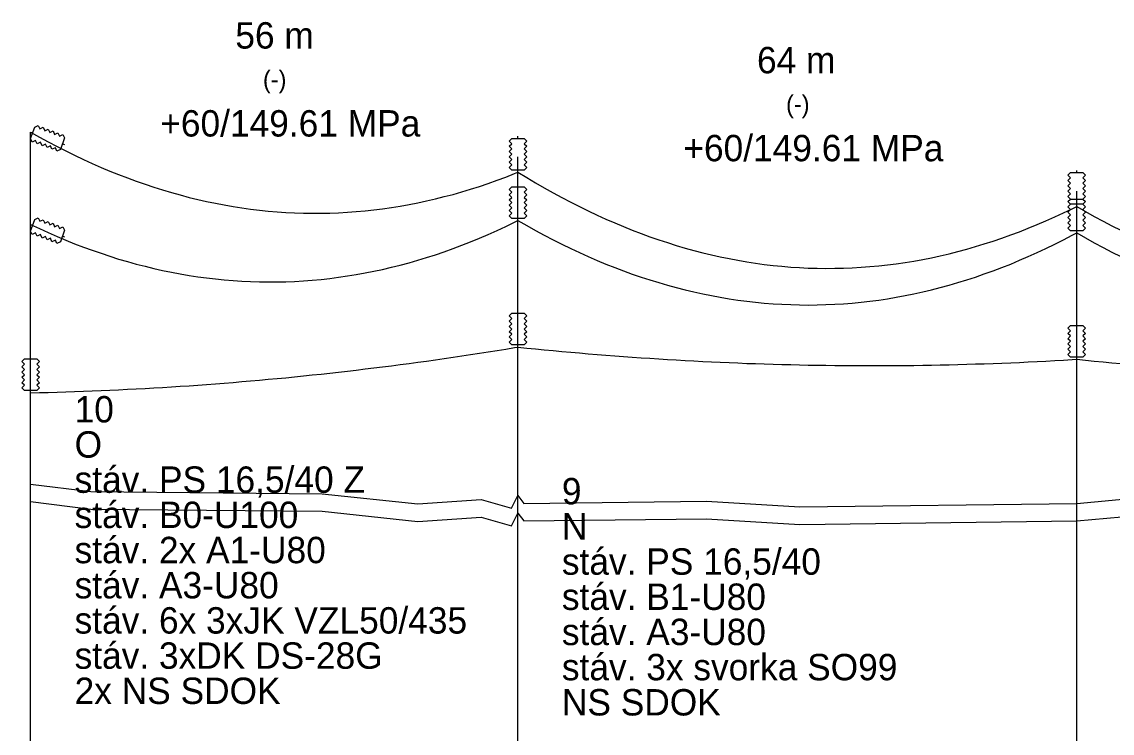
# Model space of a CAD drawing. Extents: x -21 to 625, y 813 to 990.
# Drawn here: x -1 to 122.9, y 899.9 to 980.8 of the extents above; entities that cross this region are included whole.
import ezdxf

# ---------------------------------------------------------------- set-up
doc = ezdxf.new("R2010")
doc.units = 0
for name, color, linetype in [('Vrstva 11', 7, 'Continuous'), ('Vrstva 12', 7, 'Continuous'), ('Vrstva 13', 7, 'Continuous'), ('Vrstva 14', 7, 'Continuous'), ('Vrstva 15', 7, 'Continuous'), ('Vrstva 29', 7, 'Continuous'), ('Vrstva 3', 7, 'Continuous')]:
    doc.layers.add(name, color=color, linetype=linetype)

msp = doc.modelspace()

# ---------------------------------------------------------------- linework, layer by layer
at = {"layer": 'Vrstva 11'}
for points in [[(0, 968.25), (1, 967.69), (2, 967.15), (3, 966.62), (4, 966.11), (5, 965.62), (6, 965.15), (7, 964.69), (8, 964.25), (9, 963.83), (10, 963.43), (11, 963.05), (12, 962.68), (13, 962.33), (14, 962), (15, 961.68), (16, 961.38), (17, 961.11), (18, 960.84), (19, 960.6), (20, 960.37), (21, 960.16), (22, 959.97), (23, 959.8), (24, 959.64), (25, 959.5), (26, 959.38), (27, 959.28), (28, 959.2), (29, 959.13), (30, 959.08), (31, 959.04), (32, 959.03), (33, 959.03), (34, 959.05), (35, 959.09), (36, 959.14), (37, 959.22), (38, 959.31), (39, 959.42), (40, 959.54), (41, 959.69), (42, 959.85), (43, 960.03), (44, 960.22), (45, 960.44), (46, 960.67), (47, 960.92), (48, 961.18), (49, 961.47), (50, 961.77), (51, 962.09), (52, 962.43), (53, 962.78), (54, 963.15), (55, 963.54), (55.37, 963.69)], [(55.37, 963.69), (56.37, 963.08), (57.37, 962.49), (58.37, 961.91), (59.37, 961.35), (60.37, 960.81), (61.37, 960.29), (62.37, 959.78), (63.37, 959.29), (64.37, 958.82), (65.37, 958.37), (66.37, 957.93), (67.37, 957.51), (68.37, 957.11), (69.37, 956.73), (70.37, 956.36), (71.37, 956.02), (72.37, 955.69), (73.37, 955.37), (74.37, 955.08), (75.37, 954.8), (76.37, 954.54), (77.37, 954.3), (78.37, 954.08), (79.37, 953.87), (80.37, 953.68), (81.37, 953.51), (82.37, 953.36), (83.37, 953.22), (84.37, 953.1), (85.37, 953), (86.37, 952.92), (87.37, 952.85), (88.37, 952.8), (89.37, 952.77), (90.37, 952.76), (91.37, 952.77), (92.37, 952.79), (93.37, 952.83), (94.37, 952.89), (95.37, 952.96), (96.37, 953.05), (97.37, 953.16), (98.37, 953.29), (99.37, 953.44), (100.37, 953.6), (101.37, 953.78), (102.37, 953.98), (103.37, 954.2), (104.37, 954.43), (105.37, 954.68), (106.37, 954.95), (107.37, 955.24), (108.37, 955.54), (109.37, 955.86), (110.37, 956.2), (111.37, 956.56), (112.37, 956.93), (113.37, 957.33), (114.37, 957.74), (115.37, 958.16), (116.37, 958.61), (117.37, 959.07), (118.37, 959.55), (118.87, 959.8)], [(118.87, 959.8), (119.87, 959.23), (120.87, 958.67), (121.87, 958.13), (122.87, 957.61), (123.87, 957.1)], [(0, 957.75), (1, 957.28), (2, 956.83), (3, 956.39), (4, 955.97), (5, 955.57), (6, 955.19), (7, 954.82), (8, 954.48), (9, 954.15), (10, 953.83), (11, 953.54), (12, 953.26), (13, 953), (14, 952.76), (15, 952.54), (16, 952.33), (17, 952.14), (18, 951.97), (19, 951.82), (20, 951.68), (21, 951.56), (22, 951.46), (23, 951.38), (24, 951.31), (25, 951.26), (26, 951.23), (27, 951.22), (28, 951.22), (29, 951.25), (30, 951.29), (31, 951.34), (32, 951.42), (33, 951.51), (34, 951.62), (35, 951.75), (36, 951.9), (37, 952.06), (38, 952.24), (39, 952.44), (40, 952.65), (41, 952.89), (42, 953.14), (43, 953.41), (44, 953.7), (45, 954), (46, 954.32), (47, 954.66), (48, 955.02), (49, 955.39), (50, 955.79), (51, 956.19), (52, 956.62), (53, 957.07), (54, 957.53), (55, 958.01), (55.37, 958.19)], [(0, 957.75), (1, 957.28), (2, 956.83), (3, 956.39), (4, 955.97), (5, 955.57), (6, 955.19), (7, 954.82), (8, 954.48), (9, 954.15), (10, 953.83), (11, 953.54), (12, 953.26), (13, 953), (14, 952.76), (15, 952.54), (16, 952.33), (17, 952.14), (18, 951.97), (19, 951.82), (20, 951.68), (21, 951.56), (22, 951.46), (23, 951.38), (24, 951.31), (25, 951.26), (26, 951.23), (27, 951.22), (28, 951.22), (29, 951.25), (30, 951.29), (31, 951.34), (32, 951.42), (33, 951.51), (34, 951.62), (35, 951.75), (36, 951.9), (37, 952.06), (38, 952.24), (39, 952.44), (40, 952.65), (41, 952.89), (42, 953.14), (43, 953.41), (44, 953.7), (45, 954), (46, 954.32), (47, 954.66), (48, 955.02), (49, 955.39), (50, 955.79), (51, 956.19), (52, 956.62), (53, 957.07), (54, 957.53), (55, 958.01), (55.37, 958.19)], [(55.37, 958.19), (56.37, 957.62), (57.37, 957.06), (58.37, 956.53), (59.37, 956.01), (60.37, 955.51), (61.37, 955.02), (62.37, 954.56), (63.37, 954.11), (64.37, 953.67), (65.37, 953.26), (66.37, 952.86), (67.37, 952.49), (68.37, 952.12), (69.37, 951.78), (70.37, 951.46), (71.37, 951.15), (72.37, 950.86), (73.37, 950.58), (74.37, 950.33), (75.37, 950.09), (76.37, 949.87), (77.37, 949.67), (78.37, 949.48), (79.37, 949.32), (80.37, 949.17), (81.37, 949.03), (82.37, 948.92), (83.37, 948.82), (84.37, 948.74), (85.37, 948.68), (86.37, 948.64), (87.37, 948.61), (88.37, 948.6), (89.37, 948.61), (90.37, 948.64), (91.37, 948.68), (92.37, 948.74), (93.37, 948.82), (94.37, 948.92), (95.37, 949.04), (96.37, 949.17), (97.37, 949.32), (98.37, 949.48), (99.37, 949.67), (100.37, 949.87), (101.37, 950.09), (102.37, 950.33), (103.37, 950.59), (104.37, 950.86), (105.37, 951.15), (106.37, 951.46), (107.37, 951.78), (108.37, 952.13), (109.37, 952.49), (110.37, 952.87), (111.37, 953.26), (112.37, 953.68), (113.37, 954.11), (114.37, 954.56), (115.37, 955.03), (116.37, 955.51), (117.37, 956.01), (118.37, 956.53), (118.87, 956.8)], [(55.37, 958.19), (56.37, 957.62), (57.37, 957.06), (58.37, 956.53), (59.37, 956.01), (60.37, 955.51), (61.37, 955.02), (62.37, 954.56), (63.37, 954.11), (64.37, 953.67), (65.37, 953.26), (66.37, 952.86), (67.37, 952.49), (68.37, 952.12), (69.37, 951.78), (70.37, 951.46), (71.37, 951.15), (72.37, 950.86), (73.37, 950.58), (74.37, 950.33), (75.37, 950.09), (76.37, 949.87), (77.37, 949.67), (78.37, 949.48), (79.37, 949.32), (80.37, 949.17), (81.37, 949.03), (82.37, 948.92), (83.37, 948.82), (84.37, 948.74), (85.37, 948.68), (86.37, 948.64), (87.37, 948.61), (88.37, 948.6), (89.37, 948.61), (90.37, 948.64), (91.37, 948.68), (92.37, 948.74), (93.37, 948.82), (94.37, 948.92), (95.37, 949.04), (96.37, 949.17), (97.37, 949.32), (98.37, 949.48), (99.37, 949.67), (100.37, 949.87), (101.37, 950.09), (102.37, 950.33), (103.37, 950.59), (104.37, 950.86), (105.37, 951.15), (106.37, 951.46), (107.37, 951.78), (108.37, 952.13), (109.37, 952.49), (110.37, 952.87), (111.37, 953.26), (112.37, 953.68), (113.37, 954.11), (114.37, 954.56), (115.37, 955.03), (116.37, 955.51), (117.37, 956.01), (118.37, 956.53), (118.87, 956.8)], [(118.87, 956.8), (119.87, 956.23), (120.87, 955.67), (121.87, 955.13), (122.87, 954.61), (123.87, 954.1)], [(118.87, 956.8), (119.87, 956.23), (120.87, 955.67), (121.87, 955.13), (122.87, 954.61), (123.87, 954.1)], [(0, 938.62), (1, 938.65), (2, 938.67), (3, 938.7), (4, 938.73), (5, 938.76), (6, 938.8), (7, 938.84), (8, 938.88), (9, 938.92), (10, 938.97), (11, 939.02), (12, 939.07), (13, 939.12), (14, 939.18), (15, 939.24), (16, 939.3), (17, 939.37), (18, 939.43), (19, 939.5), (20, 939.58), (21, 939.65), (22, 939.73), (23, 939.81), (24, 939.89), (25, 939.98), (26, 940.06), (27, 940.16), (28, 940.25), (29, 940.34), (30, 940.44), (31, 940.54), (32, 940.65), (33, 940.75), (34, 940.86), (35, 940.97), (36, 941.09), (37, 941.21), (38, 941.33), (39, 941.45), (40, 941.57), (41, 941.7), (42, 941.83), (43, 941.96), (44, 942.1), (45, 942.23), (46, 942.38), (47, 942.52), (48, 942.66), (49, 942.81), (50, 942.96), (51, 943.12), (52, 943.27), (53, 943.43), (54, 943.59), (55, 943.76), (55.37, 943.82)], [(55.37, 943.82), (56.37, 943.71), (57.37, 943.61), (58.37, 943.51), (59.37, 943.42), (60.37, 943.33), (61.37, 943.23), (62.37, 943.15), (63.37, 943.06), (64.37, 942.98), (65.37, 942.9), (66.37, 942.82), (67.37, 942.75), (68.37, 942.67), (69.37, 942.6), (70.37, 942.54), (71.37, 942.47), (72.37, 942.41), (73.37, 942.35), (74.37, 942.3), (75.37, 942.24), (76.37, 942.19), (77.37, 942.14), (78.37, 942.1), (79.37, 942.05), (80.37, 942.01), (81.37, 941.97), (82.37, 941.94), (83.37, 941.9), (84.37, 941.87), (85.37, 941.85), (86.37, 941.82), (87.37, 941.8), (88.37, 941.78), (89.37, 941.76), (90.37, 941.75), (91.37, 941.73), (92.37, 941.73), (93.37, 941.72), (94.37, 941.71), (95.37, 941.71), (96.37, 941.71), (97.37, 941.72), (98.37, 941.72), (99.37, 941.73), (100.37, 941.74), (101.37, 941.76), (102.37, 941.77), (103.37, 941.79), (104.37, 941.81), (105.37, 941.84), (106.37, 941.87), (107.37, 941.9), (108.37, 941.93), (109.37, 941.96), (110.37, 942), (111.37, 942.04), (112.37, 942.08), (113.37, 942.13), (114.37, 942.18), (115.37, 942.23), (116.37, 942.28), (117.37, 942.34), (118.37, 942.39), (118.87, 942.43)], [(118.87, 942.43), (119.87, 942.32), (120.87, 942.23), (121.87, 942.13), (122.87, 942.04), (123.87, 941.95)]]:
    msp.add_lwpolyline(points, dxfattribs=at)
at = {"layer": 'Vrstva 14'}
for p, q in [((0, 898.25), (0, 968.25)), ((55.37, 896.94), (55.37, 965.44)), ((118.87, 896.05), (118.87, 961.55))]:
    msp.add_line(p, q, dxfattribs=at)
at = {"layer": 'Vrstva 29'}
for points in [[(0, 967.51), (0.47, 968.82), (0.86, 969), (1.04, 968.62), (1.42, 968.8), (1.6, 968.41), (1.99, 968.59), (2.17, 968.21), (2.55, 968.39), (2.73, 968), (3.11, 968.18), (3.29, 967.8), (3.68, 967.98), (3.86, 967.59), (3.38, 966.28), (2.99, 966.1), (2.81, 966.48), (2.43, 966.3), (2.25, 966.69), (1.87, 966.51), (1.69, 966.89), (1.3, 966.71), (1.12, 967.1), (0.74, 966.92), (0.56, 967.3), (0.17, 967.12)], [(56.07, 963.94), (54.67, 963.94), (54.37, 964.24), (54.67, 964.54), (54.37, 964.84), (54.67, 965.14), (54.37, 965.44), (54.67, 965.74), (54.37, 966.04), (54.67, 966.34), (54.37, 966.64), (54.67, 966.94), (54.37, 967.24), (54.67, 967.54), (56.07, 967.54), (56.37, 967.24), (56.07, 966.94), (56.37, 966.64), (56.07, 966.34), (56.37, 966.04), (56.07, 965.74), (56.37, 965.44), (56.07, 965.14), (56.37, 964.84), (56.07, 964.54), (56.37, 964.24)], [(56.07, 963.94), (54.67, 963.94), (54.37, 964.24), (54.67, 964.54), (54.37, 964.84), (54.67, 965.14), (54.37, 965.44), (54.67, 965.74), (54.37, 966.04), (54.67, 966.34), (54.37, 966.64), (54.67, 966.94), (54.37, 967.24), (54.67, 967.54), (56.07, 967.54), (56.37, 967.24), (56.07, 966.94), (56.37, 966.64), (56.07, 966.34), (56.37, 966.04), (56.07, 965.74), (56.37, 965.44), (56.07, 965.14), (56.37, 964.84), (56.07, 964.54), (56.37, 964.24)], [(119.57, 960.05), (118.17, 960.05), (117.87, 960.35), (118.17, 960.65), (117.87, 960.95), (118.17, 961.25), (117.87, 961.55), (118.17, 961.85), (117.87, 962.15), (118.17, 962.45), (117.87, 962.75), (118.17, 963.05), (117.87, 963.35), (118.17, 963.65), (119.57, 963.65), (119.87, 963.35), (119.57, 963.05), (119.87, 962.75), (119.57, 962.45), (119.87, 962.15), (119.57, 961.85), (119.87, 961.55), (119.57, 961.25), (119.87, 960.95), (119.57, 960.65), (119.87, 960.35)], [(56.07, 958.44), (54.67, 958.44), (54.37, 958.74), (54.67, 959.04), (54.37, 959.34), (54.67, 959.64), (54.37, 959.94), (54.67, 960.24), (54.37, 960.54), (54.67, 960.84), (54.37, 961.14), (54.67, 961.44), (54.37, 961.74), (54.67, 962.04), (56.07, 962.04), (56.37, 961.74), (56.07, 961.44), (56.37, 961.14), (56.07, 960.84), (56.37, 960.54), (56.07, 960.24), (56.37, 959.94), (56.07, 959.64), (56.37, 959.34), (56.07, 959.04), (56.37, 958.74)], [(56.07, 958.44), (54.67, 958.44), (54.37, 958.74), (54.67, 959.04), (54.37, 959.34), (54.67, 959.64), (54.37, 959.94), (54.67, 960.24), (54.37, 960.54), (54.67, 960.84), (54.37, 961.14), (54.67, 961.44), (54.37, 961.74), (54.67, 962.04), (56.07, 962.04), (56.37, 961.74), (56.07, 961.44), (56.37, 961.14), (56.07, 960.84), (56.37, 960.54), (56.07, 960.24), (56.37, 959.94), (56.07, 959.64), (56.37, 959.34), (56.07, 959.04), (56.37, 958.74)], [(56.07, 958.44), (54.67, 958.44), (54.37, 958.74), (54.67, 959.04), (54.37, 959.34), (54.67, 959.64), (54.37, 959.94), (54.67, 960.24), (54.37, 960.54), (54.67, 960.84), (54.37, 961.14), (54.67, 961.44), (54.37, 961.74), (54.67, 962.04), (56.07, 962.04), (56.37, 961.74), (56.07, 961.44), (56.37, 961.14), (56.07, 960.84), (56.37, 960.54), (56.07, 960.24), (56.37, 959.94), (56.07, 959.64), (56.37, 959.34), (56.07, 959.04), (56.37, 958.74)], [(56.07, 958.44), (54.67, 958.44), (54.37, 958.74), (54.67, 959.04), (54.37, 959.34), (54.67, 959.64), (54.37, 959.94), (54.67, 960.24), (54.37, 960.54), (54.67, 960.84), (54.37, 961.14), (54.67, 961.44), (54.37, 961.74), (54.67, 962.04), (56.07, 962.04), (56.37, 961.74), (56.07, 961.44), (56.37, 961.14), (56.07, 960.84), (56.37, 960.54), (56.07, 960.24), (56.37, 959.94), (56.07, 959.64), (56.37, 959.34), (56.07, 959.04), (56.37, 958.74)], [(119.57, 957.05), (118.17, 957.05), (117.87, 957.35), (118.17, 957.65), (117.87, 957.95), (118.17, 958.25), (117.87, 958.55), (118.17, 958.85), (117.87, 959.15), (118.17, 959.45), (117.87, 959.75), (118.17, 960.05), (117.87, 960.35), (118.17, 960.65), (119.57, 960.65), (119.87, 960.35), (119.57, 960.05), (119.87, 959.75), (119.57, 959.45), (119.87, 959.15), (119.57, 958.85), (119.87, 958.55), (119.57, 958.25), (119.87, 957.95), (119.57, 957.65), (119.87, 957.35)], [(119.57, 957.05), (118.17, 957.05), (117.87, 957.35), (118.17, 957.65), (117.87, 957.95), (118.17, 958.25), (117.87, 958.55), (118.17, 958.85), (117.87, 959.15), (118.17, 959.45), (117.87, 959.75), (118.17, 960.05), (117.87, 960.35), (118.17, 960.65), (119.57, 960.65), (119.87, 960.35), (119.57, 960.05), (119.87, 959.75), (119.57, 959.45), (119.87, 959.15), (119.57, 958.85), (119.87, 958.55), (119.57, 958.25), (119.87, 957.95), (119.57, 957.65), (119.87, 957.35)], [(0, 957.01), (0.47, 958.32), (0.86, 958.5), (1.04, 958.12), (1.42, 958.3), (1.6, 957.91), (1.99, 958.09), (2.17, 957.71), (2.55, 957.89), (2.73, 957.5), (3.11, 957.68), (3.29, 957.3), (3.68, 957.48), (3.86, 957.09), (3.38, 955.78), (2.99, 955.6), (2.81, 955.98), (2.43, 955.8), (2.25, 956.19), (1.87, 956.01), (1.69, 956.39), (1.3, 956.21), (1.12, 956.6), (0.74, 956.42), (0.56, 956.8), (0.17, 956.62)], [(0, 957.01), (0.47, 958.32), (0.86, 958.5), (1.04, 958.12), (1.42, 958.3), (1.6, 957.91), (1.99, 958.09), (2.17, 957.71), (2.55, 957.89), (2.73, 957.5), (3.11, 957.68), (3.29, 957.3), (3.68, 957.48), (3.86, 957.09), (3.38, 955.78), (2.99, 955.6), (2.81, 955.98), (2.43, 955.8), (2.25, 956.19), (1.87, 956.01), (1.69, 956.39), (1.3, 956.21), (1.12, 956.6), (0.74, 956.42), (0.56, 956.8), (0.17, 956.62)], [(56.07, 944.07), (54.67, 944.07), (54.37, 944.37), (54.67, 944.67), (54.37, 944.97), (54.67, 945.27), (54.37, 945.57), (54.67, 945.87), (54.37, 946.17), (54.67, 946.47), (54.37, 946.77), (54.67, 947.07), (54.37, 947.37), (54.67, 947.67), (56.07, 947.67), (56.37, 947.37), (56.07, 947.07), (56.37, 946.77), (56.07, 946.47), (56.37, 946.17), (56.07, 945.87), (56.37, 945.57), (56.07, 945.27), (56.37, 944.97), (56.07, 944.67), (56.37, 944.37)], [(119.57, 942.68), (118.17, 942.68), (117.87, 942.98), (118.17, 943.27), (117.87, 943.58), (118.17, 943.88), (117.87, 944.18), (118.17, 944.48), (117.87, 944.77), (118.17, 945.08), (117.87, 945.38), (118.17, 945.68), (117.87, 945.98), (118.17, 946.27), (119.57, 946.27), (119.87, 945.98), (119.57, 945.68), (119.87, 945.38), (119.57, 945.08), (119.87, 944.77), (119.57, 944.48), (119.87, 944.18), (119.57, 943.88), (119.87, 943.58), (119.57, 943.27), (119.87, 942.98)], [(0.7, 938.88), (-0.7, 938.88), (-1, 939.18), (-0.7, 939.48), (-1, 939.77), (-0.7, 940.08), (-1, 940.38), (-0.7, 940.68), (-1, 940.98), (-0.7, 941.27), (-1, 941.58), (-0.7, 941.88), (-1, 942.18), (-0.7, 942.48), (0.7, 942.48), (1, 942.18), (0.7, 941.88), (1, 941.58), (0.7, 941.27), (1, 940.98), (0.7, 940.68), (1, 940.38), (0.7, 940.08), (1, 939.77), (0.7, 939.48), (1, 939.18)]]:
    msp.add_lwpolyline(points, close=True, dxfattribs=at)
for points in [[(0, 968.25), (0.23, 968.16)], [(55.37, 967.54), (55.37, 967.79)], [(55.37, 967.54), (55.37, 967.79)], [(3.62, 966.93), (3.85, 966.85)], [(55.37, 963.69), (55.37, 963.94)], [(55.37, 963.69), (55.37, 963.94)], [(118.87, 963.65), (118.87, 963.9)], [(55.37, 962.04), (55.37, 962.29)], [(55.37, 962.04), (55.37, 962.29)], [(55.37, 962.04), (55.37, 962.29)], [(55.37, 962.04), (55.37, 962.29)], [(118.87, 960.65), (118.87, 960.9)], [(118.87, 960.65), (118.87, 960.9)], [(118.87, 959.8), (118.87, 960.05)], [(55.37, 958.19), (55.37, 958.44)], [(55.37, 958.19), (55.37, 958.44)], [(55.37, 958.19), (55.37, 958.44)], [(55.37, 958.19), (55.37, 958.44)], [(0, 957.75), (0.23, 957.66)], [(0, 957.75), (0.23, 957.66)], [(118.87, 956.8), (118.87, 957.05)], [(118.87, 956.8), (118.87, 957.05)], [(3.62, 956.43), (3.85, 956.35)], [(3.62, 956.43), (3.85, 956.35)], [(55.37, 947.67), (55.37, 947.92)], [(118.87, 946.27), (118.87, 946.52)], [(55.37, 943.82), (55.37, 944.07)], [(0, 942.48), (0, 942.73)], [(118.87, 942.43), (118.87, 942.68)], [(0, 938.62), (0, 938.88)]]:
    msp.add_lwpolyline(points, dxfattribs=at)
at = {"layer": 'Vrstva 3'}
for p, q in [((0, 928.25), (6.86, 927.4)), ((6.86, 927.4), (33.13, 927.15)), ((33.13, 927.15), (43.99, 926)), ((54.66, 925.5), (55.36, 926.95)), ((55.36, 926.95), (55.37, 926.94)), ((55.37, 926.94), (56.06, 926.05)), ((118.87, 926.05), (136.97, 927.7)), ((0, 926.25), (6.86, 925.4)), ((0, 926.25), (6.86, 925.4)), ((0, 926.25), (6.86, 925.4)), ((43.99, 926), (51.19, 926.5)), ((51.19, 926.5), (54.66, 925.5)), ((56.06, 926.05), (76.8, 926.3)), ((76.8, 926.3), (87.41, 925.65)), ((87.41, 925.65), (118.87, 926.05)), ((118.87, 924.05), (136.97, 925.7)), ((118.87, 924.05), (136.97, 925.7)), ((118.87, 924.05), (136.97, 925.7)), ((6.86, 925.4), (33.13, 925.15)), ((6.86, 925.4), (33.13, 925.15)), ((6.86, 925.4), (33.13, 925.15)), ((33.13, 925.15), (43.99, 924)), ((33.13, 925.15), (43.99, 924)), ((33.13, 925.15), (43.99, 924)), ((43.99, 924), (51.19, 924.5)), ((43.99, 924), (51.19, 924.5)), ((43.99, 924), (51.19, 924.5)), ((51.19, 924.5), (54.66, 923.5)), ((51.19, 924.5), (54.66, 923.5)), ((51.19, 924.5), (54.66, 923.5)), ((54.66, 923.5), (55.36, 924.95)), ((54.66, 923.5), (55.36, 924.95)), ((54.66, 923.5), (55.36, 924.95)), ((55.36, 924.95), (55.37, 924.94)), ((55.36, 924.95), (55.37, 924.94)), ((55.36, 924.95), (55.37, 924.94)), ((55.37, 924.94), (56.06, 924.05)), ((55.37, 924.94), (56.06, 924.05)), ((55.37, 924.94), (56.06, 924.05)), ((56.06, 924.05), (76.8, 924.3)), ((56.06, 924.05), (76.8, 924.3)), ((56.06, 924.05), (76.8, 924.3)), ((76.8, 924.3), (87.41, 923.65)), ((76.8, 924.3), (87.41, 923.65)), ((76.8, 924.3), (87.41, 923.65)), ((87.41, 923.65), (118.87, 924.05)), ((87.41, 923.65), (118.87, 924.05)), ((87.41, 923.65), (118.87, 924.05))]:
    msp.add_line(p, q, dxfattribs=at)

# ---------------------------------------------------------------- texts
at = {"layer": 'Vrstva 12'}
for p in [(14.73, 967.75), (74.17, 964.94)]:
    msp.add_text('+60/149.61 MPa', height=3, dxfattribs=at).set_placement(p)
at = {"layer": 'Vrstva 13'}
for s, height, p in [('56 m', 3, (23.26, 977.75)), ('64 m', 3, (82.54, 974.94)), ('(-)', 2, (26.4, 973.25)), ('(-)', 2, (85.84, 970.44))]:
    msp.add_text(s, height=height, dxfattribs=at).set_placement(p)
at = {"layer": 'Vrstva 15'}
for s, p in [('10', (5, 935.25)), ('O', (5, 931.25)), ('stáv. PS 16,5/40 Z', (5, 927.25)), ('9', (60.37, 925.94)), ('stáv. B0-U100', (5, 923.25)), ('N', (60.37, 921.94)), ('stáv. 2x A1-U80', (5, 919.25)), ('stáv. PS 16,5/40', (60.37, 917.94)), ('stáv. A3-U80', (5, 915.25)), ('stáv. B1-U80', (60.37, 913.94)), ('stáv. 6x 3xJK VZL50/435', (5, 911.25)), ('stáv. A3-U80', (60.37, 909.94)), ('stáv. 3xDK DS-28G', (5, 907.25)), ('stáv. 3x svorka SO99', (60.37, 905.94)), ('2x NS SDOK', (5, 903.25)), ('NS SDOK', (60.37, 901.94))]:
    msp.add_text(s, height=3, dxfattribs=at).set_placement(p)

doc.saveas('drawing.dxf')
